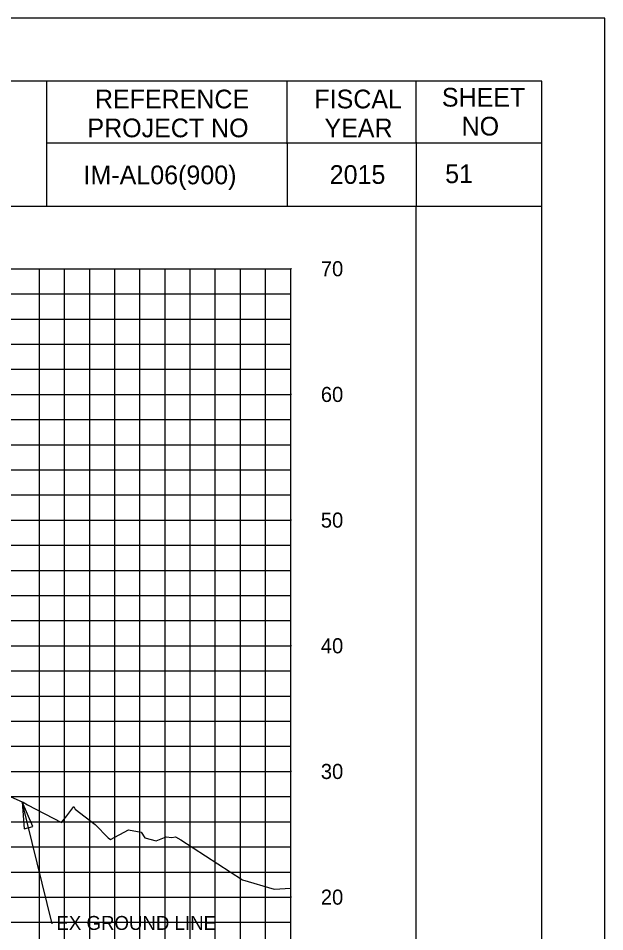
# Model space of a CAD drawing. Extents: x 1797809 to 2198143, y 249608 to 1237864.
# Drawn here: x 2195151.2 to 2195197.9, y 1237265.4 to 1237338 of the extents above; entities that cross this region are included whole.
import ezdxf

# ---------------------------------------------------------------- set-up
doc = ezdxf.new("R2010")
doc.units = 0
for name, color, linetype in [('3', 7, 'Continuous'), ('31', 7, 'Continuous'), ('60', 7, 'Continuous'), ('DESIGN - SHEET - Light Grid', 7, 'Continuous'), ('GSCOLORFILL', 7, 'Continuous'), ('GSDIMS', 7, 'Continuous'), ('GSSHT', 7, 'Continuous'), ('Level 1', 7, 'Continuous'), ('Level 45', 7, 'Continuous'), ('Level 55', 7, 'Continuous'), ('PIPETEXT', 7, 'Continuous'), ('UGUT', 7, 'Continuous')]:
    doc.layers.add(name, color=color, linetype=linetype)

msp = doc.modelspace()

# ---------------------------------------------------------------- linework, layer by layer
at = {"layer": '3'}
msp.add_line((2195153.883, 1237265.993), (2195151.483, 1237275.679), dxfattribs=at)
at = {"layer": '60'}
for p, q in [((2195172.86, 1237258.106), (2195172.86, 1237318.106)), ((2195172.92, 1237318.106), (2195172.86, 1237318.106)), ((2195172.92, 1237308.106), (2195172.86, 1237308.106)), ((2195172.92, 1237298.106), (2195172.86, 1237298.106)), ((2195172.92, 1237288.106), (2195172.86, 1237288.106)), ((2195172.92, 1237278.106), (2195172.86, 1237278.106)), ((2195172.92, 1237268.106), (2195172.86, 1237268.106))]:
    msp.add_line(p, q, dxfattribs=at)
at = {"layer": 'DESIGN - SHEET - Light Grid'}
msp.add_lwpolyline([(2195137.674, 1237281.773), (2195151.483, 1237275.679), (2195151.525, 1237275.661), (2195151.565, 1237275.666), (2195151.903, 1237275.443), (2195154.606, 1237274.035), (2195155.051, 1237274.565), (2195155.585, 1237275.306), (2195155.708, 1237275.106), (2195157.303, 1237273.896), (2195158.326, 1237272.821), (2195158.506, 1237272.691), (2195159.959, 1237273.461), (2195160.961, 1237273.278), (2195161.256, 1237272.831), (2195162.156, 1237272.593), (2195162.938, 1237272.916), (2195163.394, 1237272.863), (2195163.696, 1237272.916), (2195164.128, 1237272.677), (2195169.033, 1237269.491), (2195171.54, 1237268.746), (2195172.86, 1237268.815)], dxfattribs=at)
at = {"layer": 'GSCOLORFILL'}
msp.add_lwpolyline([(2194870.363, 1237123.036), (2195192.863, 1237123.036), (2195192.863, 1237333.036), (2194870.363, 1237333.036)], close=True, dxfattribs=at)
at = {"layer": 'GSDIMS'}
msp.add_lwpolyline([(2195151.483, 1237275.679), (2195151.651, 1237273.544), (2195152.328, 1237273.728)], close=True, dxfattribs=at)
at = {"layer": 'GSSHT'}
for p, q in [((2195042.86, 1237318.106), (2195172.86, 1237318.106)), ((2195152.86, 1237258.106), (2195152.86, 1237318.106)), ((2195154.86, 1237258.106), (2195154.86, 1237318.106)), ((2195156.86, 1237258.106), (2195156.86, 1237318.106)), ((2195158.86, 1237258.106), (2195158.86, 1237318.106)), ((2195160.86, 1237258.106), (2195160.86, 1237318.106)), ((2195162.86, 1237258.106), (2195162.86, 1237318.106)), ((2195164.86, 1237258.106), (2195164.86, 1237318.106)), ((2195166.86, 1237258.106), (2195166.86, 1237318.106)), ((2195168.86, 1237258.106), (2195168.86, 1237318.106)), ((2195170.86, 1237258.106), (2195170.86, 1237318.106)), ((2195172.86, 1237258.106), (2195172.86, 1237318.106)), ((2195042.86, 1237316.106), (2195172.86, 1237316.106)), ((2195042.86, 1237314.106), (2195172.86, 1237314.106)), ((2195042.86, 1237312.106), (2195172.86, 1237312.106)), ((2195042.86, 1237310.106), (2195172.86, 1237310.106)), ((2195042.86, 1237308.106), (2195172.86, 1237308.106)), ((2195042.86, 1237306.106), (2195172.86, 1237306.106)), ((2195042.86, 1237304.106), (2195172.86, 1237304.106)), ((2195042.86, 1237302.106), (2195172.86, 1237302.106)), ((2195042.86, 1237300.106), (2195172.86, 1237300.106)), ((2195042.86, 1237298.106), (2195172.86, 1237298.106)), ((2195042.86, 1237296.106), (2195172.86, 1237296.106)), ((2195042.86, 1237294.106), (2195172.86, 1237294.106)), ((2195042.86, 1237292.106), (2195172.86, 1237292.106)), ((2195042.86, 1237290.106), (2195172.86, 1237290.106)), ((2195042.86, 1237288.106), (2195172.86, 1237288.106)), ((2195042.86, 1237286.106), (2195172.86, 1237286.106)), ((2195042.86, 1237284.106), (2195172.86, 1237284.106)), ((2195042.86, 1237282.106), (2195172.86, 1237282.106)), ((2195042.86, 1237280.106), (2195172.86, 1237280.106)), ((2195042.86, 1237278.106), (2195172.86, 1237278.106)), ((2195042.86, 1237276.106), (2195172.86, 1237276.106)), ((2195042.86, 1237274.106), (2195172.86, 1237274.106)), ((2195042.86, 1237272.106), (2195172.86, 1237272.106)), ((2195042.86, 1237270.106), (2195172.86, 1237270.106)), ((2195042.86, 1237268.106), (2195172.86, 1237268.106)), ((2195042.86, 1237266.106), (2195172.86, 1237266.106))]:
    msp.add_line(p, q, dxfattribs=at)
msp.add_lwpolyline([(2194857.863, 1237118.036), (2195197.863, 1237118.036), (2195197.863, 1237338.036), (2194857.863, 1237338.036)], close=True, dxfattribs=at)
at = {"layer": 'Level 45'}
msp.add_lwpolyline([(2194882.86, 1237133.046), (2195182.86, 1237133.046), (2195182.86, 1237323.046), (2194882.86, 1237323.046)], close=True, dxfattribs=at)
at = {"layer": 'PIPETEXT'}
msp.add_lwpolyline([(2195182.826, 1237281.186), (2195182.835, 1237280.187)], dxfattribs=at)
msp.add_lwpolyline([(2195182.826, 1237281.186), (2195182.835, 1237280.187)], dxfattribs=at)
at = {"layer": 'UGUT'}
for p, q in [((2195153.407, 1237333.036), (2195153.407, 1237323.046)), ((2195172.57, 1237328.038), (2195172.57, 1237333.038)), ((2195182.86, 1237328.168), (2195182.86, 1237333.038)), ((2195192.863, 1237328.097), (2195153.407, 1237328.097)), ((2195172.57, 1237328.038), (2195172.57, 1237323.046)), ((2195182.86, 1237328.168), (2195182.86, 1237323.046)), ((2195192.863, 1237323.046), (2195154.617, 1237323.046))]:
    msp.add_line(p, q, dxfattribs=at)

# ---------------------------------------------------------------- texts
at = {"layer": '31'}
for s, p in [('70', (2195175.26, 1237317.506)), ('60', (2195175.26, 1237307.506)), ('50', (2195175.26, 1237297.506)), ('40', (2195175.26, 1237287.506)), ('30', (2195175.26, 1237277.506)), ('20', (2195175.26, 1237267.506))]:
    msp.add_text(s, height=1.2, dxfattribs=at).set_placement(p)
at = {"layer": 'Level 1'}
for s, height, p in [(' IM-AL06(900) ', 1.48986, (2195155.813, 1237324.827)), ('2015', 1.4899, (2195175.967, 1237324.858)), ('  51 ', 1.4899, (2195184.051, 1237324.918))]:
    msp.add_text(s, height=height, rotation=360, dxfattribs=at).set_placement(p)
at = {"layer": 'Level 55'}
msp.add_text('EX GROUND LINE', height=1.11046, dxfattribs=at).set_placement((2195154.21, 1237265.497))
at = {"layer": 'UGUT'}
for s, p in [('REFERENCE', (2195157.28, 1237330.868)), ('FISCAL', (2195174.75, 1237330.868)), ('SHEET', (2195184.897, 1237331.008)), ('PROJECT NO', (2195156.68, 1237328.568)), ('YEAR', (2195175.55, 1237328.568)), ('NO', (2195186.467, 1237328.708))]:
    msp.add_text(s, height=1.4883, dxfattribs=at).set_placement(p)

doc.saveas('drawing.dxf')
